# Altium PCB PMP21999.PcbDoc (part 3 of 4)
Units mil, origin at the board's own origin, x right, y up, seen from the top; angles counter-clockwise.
Board outline 7450 x 5800 mil, 6 copper layers (Top Layer, Signal Layer 3, Signal Layer 1, Signal Layer 2, Signal Layer 4, Bottom Layer), stack 66 mil thick; 237 components, 96 nets, 712 pads, 268 vias.
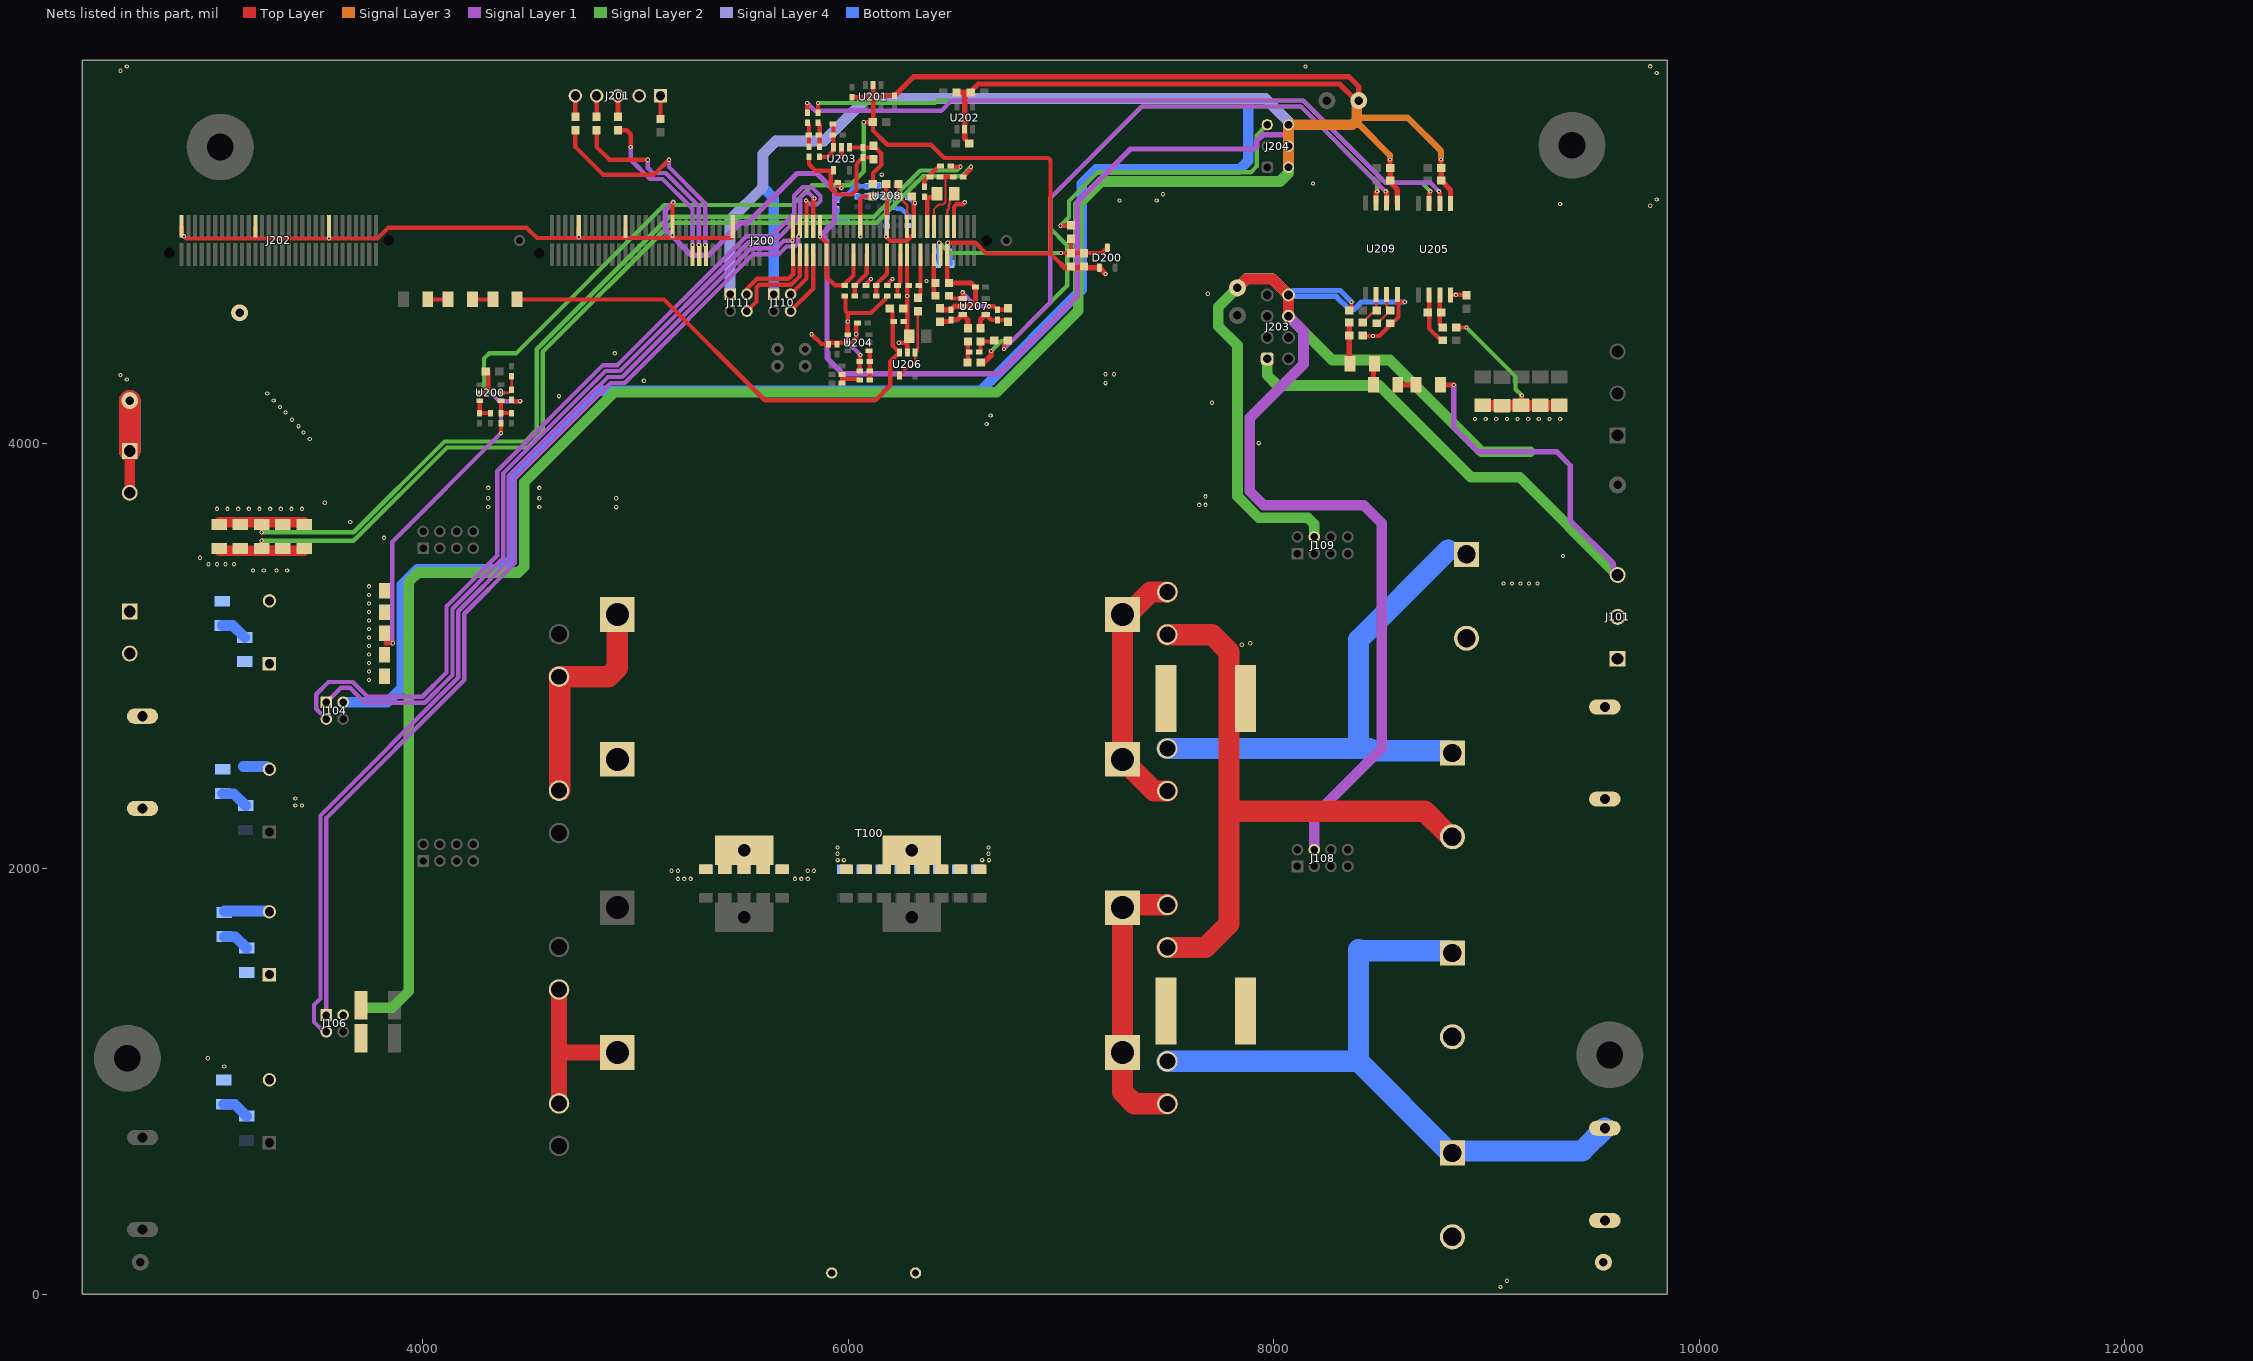
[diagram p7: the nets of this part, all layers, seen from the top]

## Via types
v1: diameter 20, hole 10, Top Layer to Bottom Layer, 268 vias

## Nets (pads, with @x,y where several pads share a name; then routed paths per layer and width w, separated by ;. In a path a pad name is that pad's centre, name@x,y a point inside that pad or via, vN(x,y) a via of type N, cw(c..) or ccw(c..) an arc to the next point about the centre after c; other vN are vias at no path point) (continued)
ISNS_REC_SEC: C220.1 R218.2 R227.2 U203.1 | length 329.1
  Top Layer w20: U203.1@6006.86,5389.75 R227.2@6126.27,5389.75 ; R218.2@6116.51,5219 6116.51,5268.53 6155.52,5307.55 6155.52,5361.72 R227.2@6119.62,5397.63
ISNS_SEC_TANK: C221.1 R200.2 R215.2 R228.2 U204.1 | length 693.2
  Top Layer w12: R228.2@6054.38,4383.53 v1@6054.38,4408.21
  Top Layer w20: R215.2@5984.38,4691.87 5984.38,4685.5 5988,4681.87 5988,4621.87 5997.81,4612.07 ; U204.1@5997.81,4509.28 5997.81,4612.07 ; C221.1@6054.38,4339.59 6054.38,4410.18 v1(6058,4413.8) ; R200.2@6184.38,4691.87 6184.38,4688.25 6108.2,4612.07 5997.81,4612.07
  Signal Layer 1 w20: v1(5998,4571.87) 5998,4473.8 v1(6058,4413.8)
Leg_1_Prim: QPL1H_S.1 QPL1L_D.1 T100.1 T100.5 | length 1077.4
  Top Layer w100: QPL1L_D.1@4641.17,2902.12 QPL1L_D.1@4644.2,2902.12 ; QPL1H_S.1@4644.2,2367.09 QPL1L_D.1@4644.2,2902.12 ; T100.1@4915.35,3194.88 4915.35,2944.02 4873.46,2902.12 QPL1L_D.1@4644.2,2902.12
Leg_1_Sec: QSL1H_S.1 QSL1L_D.1 T100.4 T100.8 | length 1316
  Top Layer w100: QSL1H_S.1@7500,894.88 7345.12,894.88 7289.37,950.63 T100.8@7289.37,1135.83 T100.4@7289.37,1816.93 7302.36,1829.92 QSL1L_D.1@7500,1829.92
Leg_2_Prim: QPL2H_S.1 QPL2L_D.1 T100.2 | length 812.9
  Top Layer w75: QPL2L_D.1@4641.17,1432.05 4641.17,1130 ; QPL2H_S.1@4644.2,897.01 4641.17,900.04 4641.17,1130 ; T100.2@4915.35,1135.83 4646.99,1135.83 4641.17,1130
Leg_2_Sec: QSL2H_S.1 QSL2L_D.1 T100.3 T100.7 | length 1191.9
  Top Layer w100: QSL2H_S.1@7500,2364.96 7438.19,2364.96 T100.3@7289.37,2513.78 7289.37,3168.11 7421.26,3300 QSL2L_D.1@7500,3300
NetC100_2: C100.2 C105.2 C108.2 C109.2 C110.2 C113.2 C114.2 C115.2 C122.2 C126.2 C128.2 C130.2 C132.2 C134.2 C136.2 C138.2 pad.1@6299.21,2086.61
  other v1: 5950.92,2040 5980,2040 6630,2040 6661.81,2040 5950,2070 6660,2070 5950,2100 6659.37,2100
NetC101_2: C101.2 C111.1 R105.1 R110.2
  other v1: 3067.48,1070 2990,1109.29
NetC102_2: C102.2 C112.1 R106.1 R111.2 | length 125.2
  Bottom Layer w50: 3157.48,2480.18 3264.94,2480.18 C102.2@3277.48,2467.64
NetC127_1: C127.1 C129.1 C131.1 C133.1 C135.1 C137.1 C139.1 C141.1 C143.1 C145.1 pad.1@5511.81,2086.61
  other v1: 5200,1952.35 5230,1952.35 5260,1952.35 5750.6,1952.35 5780,1952.35 5810,1952.35 5169.85,1990 5200,1990 5810,1990 5840,1990
NetC200_1: C200.1 J200.24 R200.1 | length 198.9
  Top Layer w20: R200.1@6231.63,4691.87 C200.1@6231.63,4741.87 6245.52,4755.77 J200.24@6245.52,4885.06
NetC202_1: C202.1 C204.1 C205.1 D200.3 J200.12 R206.1 R216.2 | length 1040.9
  Top Layer w20: v1(6428,4941.87) 6434.5,4935.38 J200.12@6434.5,4885.06 ; v1(6999.5,4893.37) R216.2@7048,4893.37 ; R206.1@7048,4960.38 R216.2@7048,4893.37 ; D200.3@7218,4919.12 7192.26,4893.37 R216.2@7048,4893.37
  Signal Layer 2 w20: v1(6428,4941.87) 6476.51,4893.37 v1(6999.5,4893.37)
  Bottom Layer w20: C205.1@6424.38,4849.75 C204.1@6424.38,4901.87 6424.38,4938.25 v1(6428,4941.87)
NetC203_1: C203.1 R202.2 R211.1 | length 132.7
  Top Layer w20: R211.1@6358,5205.5 6358,5233.53 6426.35,5301.87 R202.2@6434.38,5301.87
NetC203_2: C203.2 J200.13 R209.2 | length 331.2
  Top Layer w10: J200.13@6403,5018.92 6403,5099.09 6425.78,5121.87 6447.55,5121.87 6458,5132.33 6458,5251.87
  Top Layer w20: C203.2@6431.63,5251.87 6458,5251.87 R209.2@6494.38,5251.87
NetC206_2: C206.2 J200.14 R207.1 | length 184.3
  Top Layer w20: R207.1@6403,4700.77 J200.14@6403,4885.06
NetC207_1: C207.1 J200.18 R208.1 | length 206.7
  Top Layer w20: R208.1@6328,4683.37 6340.01,4695.38 J200.18@6340.01,4885.06
NetC208_1: C208.1 J200.21 R214.2 | length 217.7
  Top Layer w12: R214.2@6236.51,5219 C208.1@6236.51,5159 6278,5117.5 6278,5019.9 J200.21@6277.02,5018.92
NetC209_1: C209.1 J200.27 R218.1 | length 197
  Top Layer w12: C209.1@6176.51,5159 C209.1@6179.5,5159
  Top Layer w20: C209.1@6179.5,5161.99 R218.1@6179.5,5219 ; J200.27@6182.53,5018.92 C209.1@6182.53,5155.97
NetC210_1: C210.1 J200.34 R215.1 | length 217.2
  Top Layer w20: R215.1@6031.63,4691.87 C210.1@6031.63,4741.87 6032.1,4741.87 6050.76,4760.53 6050.76,4761.09 6061.23,4771.56 6061.78,4771.56 6088.04,4797.82 J200.34@6088.04,4885.06
NetC211_1: C211.1 J200.28 R217.1 | length 214.3
  Top Layer w20: R217.1@6131.63,4691.87 C211.1@6131.63,4741.87 6131.63,4745.5 6182.53,4796.4 J200.28@6182.53,4885.06
NetC220_2: C220.2 R227.1 R234.2 U203.4 | length 604
  Top Layer w20: R234.2@5816.35,5345.38 5816.35,5310.65 5846.88,5280.13 5929.68,5280.13 5918,5268.45 5918,5199 5948.38,5168.63 5980.59,5168.63 5980.96,5169 6018,5169 6039.82,5190.81 6039.82,5313.38 C220.2@6068.95,5342.51 R227.1@6118.95,5342.51
NetC221_2: C221.2 R228.1 R231.2 U204.4 | length 129.2
  Top Layer w20: R231.2@6101.63,4301.87 C221.2@6101.63,4339.59 U204.4@6101.63,4431.05
NetC227_1: C227.1 R230.2 R231.1 | length 122.8
  Top Layer w20: R230.2@5971.63,4281.87 5971.63,4301.87 ; C227.1@5971.63,4321.87 5971.63,4301.87 ; R231.1@6054.38,4301.87 5971.63,4301.87
NetC228_1: C228.1 R232.2 U205.2 | length 245
  Top Layer w20: U205.2@8730.89,4697.01 8730.89,4539.06 8786.4,4483.54 R232.2@8794.9,4483.54
NetC228_2: C228.2 R237.2 U205.3 | length 159.3
  Top Layer w20: U205.3@8780.89,4697.01 8780.89,4557.56 R237.2@8794.9,4543.54
NetC229_1: C229.1 R233.2 R234.1 | length 116.2
  Top Layer w20: R233.2@5808,5505.38 5816.35,5497.03 R234.1@5816.35,5392.62
NetC229_2: C229.2 R235.2 R236.1 | length 116.2
  Top Layer w20: R235.2@5858,5505.38 5866.35,5497.03 R236.1@5866.35,5392.62
NetC230_1: C230.1 R236.2 R238.2 U203.3 | length 196.9
  Top Layer w19.68: R236.2@5866.35,5345.38 5901.51,5345.38 5931.55,5375.42 U203.3@5931.55,5390.27 C230.1@5931.55,5494.7
NetC232_2: C232.2 R242.1 R253.2 U207.4 | length 199.5
  Top Layer w20: U207.4@6646.55,4605.46 6672.77,4579.23 R242.1@6752.41,4579.23
  Top Layer w25: R253.2@6622.41,4532.72 6622.41,4581.32 U207.4@6646.55,4605.46
NetC233_1: C233.1 R244.2 R254.2 U208.1 | length 294.1
  Bottom Layer w20: C233.1@6041.37,5160.14 6199.74,5160.14 6219.85,5140.02 U208.1@6219.85,5111.68 6229.66,5101.87 6250.01,5101.87 R254.2@6281.63,5070.26
NetC233_2: C233.2 R244.1 R249.2 U208.4 | length 216.8
  Bottom Layer w20: R249.2@5948,5145.5 5973.63,5171.13 5997.26,5171.13 C233.2@6033.52,5207.39 ; C233.2@6041.37,5207.39 6140.37,5207.39 U208.4@6145.05,5212.07
NetC240_1: C240.1 R248.2 R249.1 | length 102.8
  Bottom Layer w20: R249.1@5948,5098.25 R248.2@5948,5045.5 C240.1@5998,5045.5
NetC241_1: C241.1 R246.1 R255.2 U206.3 | length 2374.7
  Top Layer w20: R246.1@4444.33,4675.42 5134.46,4675.42 5608,4201.87 6128,4201.87 6198,4271.87 6198,4383.41 U206.3@6240.6,4426.01 6210.13,4456.48 6210.13,4576.13 6208,4578.25 6208,4620.38 R255.2@6196.51,4631.87
NetC242_1: C242.1 R251.2 U209.2 | length 161.1
  Top Layer w12: R251.2@8417.89,4566.34 8418.7,4566.34 8451.45,4599.1 8451.45,4599.9 8478.6,4627.05 8481.4,4627.05 U209.2@8481.4,4698.98
NetC242_2: C242.2 R259.2 U209.3 | length 170.1
  Top Layer w12: R259.2@8484.9,4563.54 8487.89,4563.54 C242.2@8547.89,4623.54 8531.4,4640.04 U209.3@8531.4,4698.98
NetC243_1: C243.1 R252.2 R253.1 | length 108
  Top Layer w20: C243.1@6622.41,4435.48 R253.1@6622.41,4477.6 6682.24,4477.6 R252.2@6686.51,4481.87
NetC243_2: C243.2 R256.2 R257.1 | length 100.5
  Top Layer w20: R256.2@6562.41,4384.98 R257.1@6562.41,4485.48
NetC244_1: C244.1 R257.2 R260.2 U207.3 | length 202.7
  Top Layer w25: R260.2@6432.41,4571.36 6474.54,4571.36 C244.1@6482.41,4579.23 6512.06,4579.23 U207.3@6538.28,4605.46 6562.41,4581.32 R257.2@6562.41,4532.72
NetJ200_15: J200.15 R204.1 R211.2 | length 166.5
  Top Layer w19.68: R211.2@6368,5155.38 R204.1@6401.51,5155.38 ; J200.15@6371.51,5018.92 6371.51,5151.87
NetJ201_1: J201.1 R219.1 | length 98.5
  Top Layer w20: R219.1@5118,5523.37 J201.1@5118,5621.87
NetJ201_3: J201.3 R220.2 | length 88.5
  Top Layer w25: R220.2@4918,5533.37 J201.3@4918,5621.87
NetJ201_4: J201.4 R221.2 | length 88.5
  Top Layer w20: R221.2@4818,5533.37 J201.4@4818,5621.87
NetJ201_5: J201.5 R224.2 | length 88.5
  Top Layer w20: R224.2@4718,5533.37 J201.5@4718,5621.87
NetR100_1: R100.1 R105.2 | length 130.1
  Bottom Layer w50: R105.2@3066.3,892.91 3117.4,892.91 R100.1@3173.23,837.09
NetR101_1: R101.1 R106.2 | length 131.4
  Bottom Layer w50: R106.2@3060,2352.91 3112.4,2352.91 R101.1@3168.23,2297.09
NetR110_1: R110.1 R114.2 | length 127.8
  Bottom Layer w50: R114.2@3067.48,1680.34 3119.97,1680.34 R110.1@3173.23,1627.09
NetR111_1: R111.1 R115.2 | length 127.4
  Bottom Layer w50: R115.2@3059.21,3142.91 3107.64,3142.91 R111.1@3163.46,3087.09
NetR201_1: R201.1 R212.2 U200.4 | length 108.8
  Top Layer w20: R212.2@4368.52,4141.13 R201.1@4418.52,4141.13 ; R212.2@4368.72,4141.33 U200.4@4368.72,4200.11
NetR203_1: R203.1 R213.2 U200.5 | length 118.2
  Top Layer w12: U200.5@4368.72,4237.51 4404.9,4237.51 R213.2@4418.52,4251.13 R203.1@4418.52,4313.89
NetR205_1: R205.1 R210.2 U200.3 | length 108.8
  Top Layer w20: U200.3@4268.33,4200.11 4268.33,4141.33 R210.2@4318.33,4141.33
NetR233_1: R233.1 U205.6 | length 3286
  Top Layer w20: R233.1@5808,5552.62 v1(5808,5599) ; v1(8776.4,5183.54) 8780.89,5179.06 U205.6@8780.89,5126.14
  Signal Layer 1 w20: v1(5808,5599) 5845.13,5561.87 6437.37,5561.87 6485.5,5610 8139.36,5610 8525.82,5223.54 8736.4,5223.54 v1(8776.4,5183.54)
NetR235_1: R235.1 U205.7 | length 3165.7
  Top Layer w20: R235.1@5858,5552.62 v1(5858,5599) ; U205.7@8730.89,5126.14 8730.89,5178.03 v1(8736.4,5183.54)
  Signal Layer 2 w20: v1(5858,5599) 6408.75,5599 6419.75,5610 8139.36,5610 8525.82,5223.54 8696.4,5223.54 v1(8736.4,5183.54)
NetR240_1: R240.1 R243.2 | length 95.8
  Top Layer w20: R240.1@4024.33,4675.42 R243.2@4120.16,4675.42
NetR241_1: R241.1 R245.2 | length 85.8
  Top Layer w25: R245.2@8583.48,4273.54 R241.1@8669.31,4273.54
NetR243_1: R243.1 R246.2 | length 95.8
  Top Layer w20: R243.1@4234.33,4675.42 R246.2@4330.16,4675.42
NetR245_1: R245.1 R250.2 | length 95.8
  Top Layer w25: R245.1@8469.31,4273.54 R250.2@8469.31,4369.37
NetR250_1: R250.1 R251.1 R258.2 | length 171.3
  Top Layer w25: R250.1@8354.9,4377.95 R258.2@8354.9,4506.34 R251.1@8354.9,4549.26
NetR252_1: R252.1 U209.6 | length 2822.6
  Top Layer w20: v1(6732.41,4442.86) 6732.41,4464.79 R252.1@6749.5,4481.87
  Top Layer w25: v1(8526.4,5183.54) 8531.4,5178.54 U209.6@8531.4,5128.11
  Signal Layer 1 w20: v1(6732.41,4442.86) 6950,4660.44 6950,5152.13 7380,5582.13 8127.81,5582.13 v1(8526.4,5183.54)
NetR256_1: R256.1 U209.7 | length 2980.3
  Top Layer w25: R256.1@6616.04,4378.6 6638.16,4378.6 6672.41,4412.86 v1(6672.41,4432.86) ; U209.7@8481.4,5128.11 8481.4,5178.54 v1(8486.4,5183.54)
  Signal Layer 2 w20: v1(6672.41,4432.86) 6719.56,4480 6769.56,4480 7030,4740.44 7030,4929.46 6950.76,5008.7 6950.76,5152.89 7380,5582.13 8127.81,5582.13 8486.4,5223.54 v1(8486.4,5183.54)
PGND: C111.2 C112.2 C120.2 C121.2 C147.2 C200.2 C201.1 C202.2 C204.2 C205.2 C206.1 C207.2 C208.2 C209.2 C210.2 C211.2 C214.1 C215.2 C216.1 C217.2 C218.1 C219.1 C223.2 C224.1 C225.2 C226.2 C231.2 C234.2 C236.2 C237.1 C238.2 C239.2 C241.2 C244.2 C245.2 C246.2 D200.1 J104.2 J106.2 J110.1 J111.1 J200.7 J200.10 J200.19 J200.22 J200.35 J200.38 J200.46 J200.47 J200.65 J200.83 J200.97 J200.111 J201.2 J202.135 J202.157 J202.179 J204.2 J204.4 J204.6 R103.1 R107.1 R109.1 R113.1 R114.1 R115.1 R117.1 R118.1 R119.1 R120.1 R121.1 R122.1 R209.1 R212.1 R213.1 R216.1 R239.1 R255.1 R260.1 R261.1 TP105.1 TP106.1 U200.2 U201.2 U202.2 U203.2 U204.2 U205.5 U206.2 U207.2 U208.2 U209.5 | length 50762.4
  Top Layer w19.68: v1@3560.48,4964.35 J202.135@3560.48,5019.79
  Top Layer w20: J202.179@2867.57,4982.31 J202.179@2867.57,5019.79 ; 2888,4961.87 3788,4961.87 3838,5011.87 4489.82,5011.87 4538,4963.69 5449.82,4963.69 J200.65@5458,4971.87 ; J202.157@3214.03,4967.9 J202.157@3214.03,5019.79 ; R109.1@3243.46,3494.17 R109.1@3243.46,3504.02 v1(3243.46,3541.1) ; 3825.71,3059.25 v1(3860,3059.25) ; U200.2@4268.33,4237.51 4298.52,4237.51 v1(4308.52,4247.51) C201.1@4308.52,4337.51 ; v1(4368.52,4047.51) R212.1@4368.52,4093.89 ; R213.1@4418.52,4203.89 4424.9,4197.51 v1(4458.52,4197.51) ; v1(4733.71,4967.98) J200.111@4733.71,5018.92 ; J200.97@4954.19,4967.51 J200.97@4954.19,5018.92 ; J200.83@5174.66,4967.03 J200.83@5174.66,5018.92 5174.66,5128.53 v1(5178,5131.87) ; J200.65@5458.12,4971.99 J200.65@5458.12,5018.92 ; v1(5828,4511.87) 5874.38,4465.5 R239.1@5908,4465.5 ; J200.47@5867.57,5018.92 5867.57,4972.31 v1(5868,4971.87) 5899.07,4940.81 J200.46@5899.07,4885.06 5899.07,4780.81 5938,4741.87 C210.2@5984.38,4741.87 5984.38,4747.47 6025.05,4788.14 J200.38@6025.05,4885.06 ; R239.1@5914.38,4471.87 U204.2@5997.81,4471.87 6018,4471.87 6038,4491.87 v1(6038,4511.87) C226.2@6038,4558.37 ; C217.2@6018,5625.38 6114.39,5625.38 ; v1(6058,4971.87) 6056.55,4973.33 J200.35@6056.55,5018.92 6056.55,5147.54 6068,5159 C209.2@6116.51,5159 ; v1(6073.59,5508.02) C214.1@6115.52,5508.02 ; C211.2@6084.38,4741.87 6088,4745.5 6088,4751.87 v1(6108,4771.87) ; C214.1@6116.51,5509 6116.51,5469.71 6183.59,5402.62 6389.57,5402.62 6452.05,5340.14 6940.32,5340.14 6950.76,5329.7 6950.76,4891.87 ; C214.1@6118,5510.5 U201.2@6118,5683.13 ; 6121.63,5632.62 C215.2@6218,5632.62 ; v1(6178,4971.87) 6198,4951.87 6278,4951.87 6308.52,4982.39 J200.19@6308.52,5018.92 6308.52,5149.98 C208.2@6299.5,5159 ; C200.2@6184.38,4741.87 6184.38,4748.25 v1(6208,4771.87) ; v1(6238,4471.87) 6278,4471.87 U206.2@6278,4426.01 ; C207.2@6277.02,4749.24 J200.22@6277.02,4885.06 ; C234.2@6278,4516.01 C207.2@6278,4735.5 ; C206.1@6466,4760.77 J200.10@6466,4885.06 v1@6466,4939.87 ; v1(6468,4941.87) 6598,4941.87 6648,4891.87 6950.76,4891.87 ; J200.7@6497.49,5018.92 6497.49,5111.36 6508.63,5122.5 6538.63,5122.5 v1(6548,5131.87) ; R209.1@6541.63,5251.87 6578,5288.25 v1(6578,5299) ; 7000.76,4841.87 6950.76,4891.87
  Top Layer w25: C225.2@5951.71,5226.13 5951.71,5215.3 v1(5968,5199) ; v1(5968.95,5345.97) U203.2@5968.95,5390.27 ; C215.2@6218,5632.62 6307.26,5721.87 8354.52,5721.87 8400,5676.4 TP106.1@8400,5610 8388.07,5610 8310,5688.07 6611.38,5688.07 6576.51,5653.21 C216.1@6576.51,5649 C218.1@6509.5,5649 ; R260.1@6432.41,4626.48 C244.2@6482.41,4626.48 6498.79,4642.86 U207.2@6538.28,4642.86 6572.41,4642.86 6598.79,4669.23 C238.2@6598.79,4732.86 6578.79,4752.86 C206.1@6473.91,4752.86 ; 6548,5648.98 U202.2@6548,5474.87 6548,5430.5 C219.1@6569.5,5409 ; 7000.76,4841.87 7018,4824.63 D200.1@7180.6,4824.63 v1(7210,4795.23) ; C236.2@8546.4,5295.04 v1(8546.4,5333.54) ; C236.2@8547.89,5293.54 8547.89,5224.85 8581.4,5191.34 U209.5@8581.4,5128.11 ; C223.2@8786.4,5295.04 v1(8786.4,5333.54) ; C223.2@8787.89,5293.54 C224.1@8787.89,5233.54 8830.89,5190.55 U205.5@8830.89,5126.14
  Top Layer w50: R107.1@3043.46,3494.17 3243.46,3494.17 R113.1@3443.46,3494.17
  Signal Layer 1 w20: v1(3860,3059.25) 3857.95,3061.3 3857.95,3536.94 v1(4368.52,4047.51) 4368.52,4197.31 ; v1(4308.52,4247.51) 4358.52,4197.51 v1(4458.52,4197.51)
  Signal Layer 1 w25: v1(5178,5131.87) 5140.88,5094.75 5140.88,5005.49 5263.49,4882.87 5342.55,4882.87 5494.91,5035.24 5527.95,5035.24 5760.26,5267.55 5853.95,5267.55 5936.19,5185.31 5936.19,5038.6 5870.5,4972.91 5879.18,4972.91 5900.88,4951.21 5900.88,4400.1 5974.41,4326.56 6710.87,4326.56 7077.13,4692.81 7077.13,5133.62 7326.38,5382.87 7910,5382.87 7920,5392.87 7920,5420 7949,5449 8069.78,5449
  Signal Layer 1 w50: J204.2@8069.78,5296.48 J204.4@8069.78,5396.48 8069.78,5449 J204.6@8069.78,5496.48
  Signal Layer 2 w20: v1(3243.46,3541.1) 3675.72,3541.1 4114.62,3980 4492.5,3980 4564.62,4052.12 4564.62,4430 5170.74,5036.13 6132.84,5036.13 6350.71,5254 6533,5254 v1(6578,5299) ; v1(4308.52,4247.51) 4288.52,4267.51 4288.52,4397.51 4313.14,4422.13 4438.48,4422.13 5136.11,5119.75 5738,5119.75 5830.13,5211.87 6008,5211.87 6073.59,5277.46 v1(6073.59,5508.02)
  Signal Layer 2 w50: 3720,1346.04 3856.79,1346.04 3935.04,1424.29 3935.04,3348.19 3978.85,3392 4450,3392 4477.15,3419.15 4477.15,3816.06 4901.08,4240 6698.13,4240 7080.8,4622.68 7080.8,5120.8 7190,5230 8030,5230 8069.78,5269.78 J204.2@8069.78,5296.48 J204.4@8069.78,5396.48 J204.6@8069.78,5496.48
  Signal Layer 3 w29.53: 8370,5496.48 8403.52,5496.48 8546.4,5353.6 v1(8546.4,5333.54) ; 8390,5530 8629.94,5530 8786.4,5373.54 v1(8786.4,5333.54)
  Signal Layer 3 w50: J204.2@8069.78,5296.48 J204.4@8069.78,5396.48 J204.6@8069.78,5496.48 8370,5496.48 8390,5516.48 8390,5530 TP106.1@8390,5600
  Signal Layer 4 w20: 3243.46,3522.56 v1(3243.46,3541.1)
  Signal Layer 4 w50: J111.1@5444.68,4699.37 5444.68,5049.17 5598.79,5203.28 5598.79,5358.79 5660,5420 5884.8,5420 6084.8,5620 7960,5620 8069.78,5510.22 J204.6@8069.78,5496.48 J204.4@8069.78,5396.48 J204.2@8069.78,5296.48
  Bottom Layer w20: v1(6178,4971.87) 6178,5036.94 ; C239.2@6278,5158.25 6308.24,5128.02 v1(6314.11,5128.02) ; v1(6468,4941.87) 6471.63,4938.25 C204.2@6471.63,4901.87 ; C205.2@6479.5,4841.87 C204.2@6479.5,4894
  Bottom Layer w25: 6181.63,5036.94 U208.2@6181.63,5110.85
  Bottom Layer w50: R114.1@3067.48,1800.93 3280,1800.93 C111.2@3280,1797.64 ; J104.2@3626.46,2782.13 3834.25,2782.13 3902.13,2850 3902.13,3333.97 3976.03,3407.87 4373.17,3407.87 4419.27,3453.97 4419.27,3840.03 4826.03,4246.79 6623.07,4246.79 7098.06,4721.78 7098.06,5219.91 7166.03,5287.87 7840,5287.87 7880,5327.87 7880,5620 ; J110.1@5650.63,4699.37 5650.63,5151.44 5600,5202.07 5600,5360 5660,5420 5884.8,5420 6084.8,5620 7880,5620 ; J204.2@8069.78,5296.48 J204.4@8069.78,5396.48 J204.6@8069.78,5496.48 8069.78,5510.22 7960,5620 7880,5620
  other v1: 3401.95,2297.09 3433.46,2297.09 3401.95,2330 3747.95,2886.85 3747.95,2926.85 3747.95,2966.85 3747.95,3006.85 3747.95,3046.85 3747.95,3086.85 3747.95,3126.85 3747.95,3166.85 3747.95,3206.85 3747.95,3246.85 3747.95,3286.85 3747.95,3326.85 3203.46,3401.1 3253.46,3401.1 3313.46,3401.1 3363.46,3401.1 2993.46,3431.1 3033.46,3431.1 3073.46,3431.1 3113.46,3431.1 2953.46,3461.1 3818.9,3554.96 3660,3629.96 4910,3699.03 4308.67,3700 4548.67,3700 3540,3720 4308.67,3741.2 4548.67,3741.2 4910,3741.2 4308.67,3790 4548.67,3790 6651.02,4090 6669.74,4130 4641.17,4221.01 7210,4281.87 5040,4293.52 2610,4298.91 2580,4320 7210,4324 7250,4324 4903.08,4422.13 6278,4691.87 6368,4761.87 3560,4961.87 2877.79,4972.09 5174.66,4977 9770,5115.5 9346.4,5123.54 7275.07,5140.22 7450,5140 9800,5145.5 7480,5170 8185.39,5220 6158,5261.87 6548,5520 9800,5740 2580,5750 2610,5770 8150,5770 9770,5771
PRI_FAULT: J200.74 R224.1 | length 1120.3
  Top Layer w20: R224.1@4718,5470.38 4718,5391.87 4848,5261.87 5088,5261.87 v1(5158,5331.87) ; v1(5328,4931.87) 5332.14,4927.74 J200.74@5332.14,4885.06
  Signal Layer 1 w20: v1(5158,5331.87) 5158,5297.46 5328,5127.46 v1(5328,4931.87)
PWM1A: J104.1 J200.49 | length 3954.4
  Top Layer w20: J200.49@5836.07,5018.92 5836.07,5143.88 v1(5842.41,5150.22)
  Signal Layer 1 w20: J104.1@3547.72,2782.13 3615.59,2850 3660,2850 3730,2780 4010,2780 4140,2910 4140,3221.48 4378.52,3460 4378.52,3856.91 4860.23,4338.62 4927.16,4338.62 5532.66,4944.12 5651.41,4944.12 5774.54,5067.25 5774.54,5152.96 5798,5176.43 5816.21,5176.43 v1(5842.41,5150.22)
PWM1B: J104.3 J200.51 | length 4261.8
  Top Layer w20: v1(5802.41,5140.22) 5804.58,5138.05 J200.51@5804.58,5018.92
  Signal Layer 1 w20: J104.3@3547.72,2703.38 3547.58,2703.38 3500,2750.96 3500,2820 3557.87,2877.87 3671.55,2877.87 3741.55,2807.87 3998.45,2807.87 4112.13,2921.55 4112.13,3233.02 4350.65,3471.55 4350.65,3868.46 4848.69,4366.5 4915.62,4366.5 5521.11,4971.99 5638.66,4971.99 5746.67,5080 5746.67,5164.51 5786.46,5204.3 5827.75,5204.3 5870.29,5161.77 5870.29,5138.67 5853.96,5122.35 5820.29,5122.35 v1(5802.41,5140.22)
PWM2A: J106.1 J200.53 | length 4760.5
  Top Layer w20: v1(5768,4971.87) 5773.08,4976.95 J200.53@5773.08,5018.92
  Signal Layer 1 w20: J106.1@3547.72,1312.05 3547.72,2238.88 4195.75,2886.91 4195.75,3198.38 4434.27,3436.91 4434.27,3833.82 4883.32,4282.87 4950.25,4282.87 5555.75,4888.37 5674.5,4888.37 5710.13,4924 5749.55,4924 5765.88,4940.33 5765.88,4969.75 v1(5768,4971.87)
PWM2B: J106.3 J200.55 | length 4869.5
  Top Layer w20: v1(5738,4951.87) 5740.13,4954 5740.13,5017.46 J200.55@5741.59,5018.92
  Signal Layer 1 w20: J106.3@3536.69,1233.31 3490,1280 3490,1360 3519.84,1389.84 3519.84,2250.42 4167.87,2898.45 4167.87,3209.93 4406.4,3448.45 4406.4,3845.37 4871.78,4310.75 4938.71,4310.75 5544.2,4916.24 5662.95,4916.24 5698.58,4951.87 v1(5738,4951.87)
PWM3A: J110.4 J200.50 | length 308.6
  Top Layer w20: J110.4@5729.37,4620.63 5836.07,4727.33 J200.50@5836.07,4885.06
PWM3B: J110.3 J200.52 | length 216.8
  Top Layer w20: J110.3@5729.37,4699.37 5804.58,4774.58 J200.52@5804.58,4885.06
PWM4A: J111.4 J200.54 | length 454.7
  Top Layer w20: J111.4@5524.37,4620.63 5569.61,4665.87 5569.61,4731.38 5582.83,4744.61 5731.8,4744.61 5773.08,4785.89 J200.54@5773.08,4885.06
PWM4B: J111.3 J200.56 | length 362.9
  Top Layer w20: J111.3@5524.37,4699.37 5524.37,4725.57 5571.28,4772.48 5720.25,4772.48 5741.59,4793.81 J200.56@5741.59,4885.06
RTN: J103.1 J103.2 R103.2 R107.2 R109.2 R113.2 R117.2 R202.1 TP104.1 | length 5382
  Top Layer w20: v1(3243.46,3581.1) R109.2@3243.46,3618.19 R109.2@3243.46,3628.03 ; R202.1@6481.63,5301.87 6484.5,5299 v1(6528,5299)
  Top Layer w50: J103.2@2623.46,3766.54 J103.1@2623.46,3963.39 ; R107.2@3043.46,3628.03 3243.46,3628.03 R113.2@3443.46,3628.03
  Top Layer w100: J103.1@2623.46,3963.39 TP104.1@2623.46,4200
  Signal Layer 2 w20: v1(3243.46,3581.1) 3676.3,3581.1 4103.07,4007.87 4480.95,4007.87 4536.74,4063.67 4536.74,4441.55 5159.2,5064 6121.29,5064 6339.16,5281.87 6510.88,5281.87 v1(6528,5299)
  Bottom Layer w100: J103.1@2623.46,3963.39 TP104.1@2623.46,4200
  other v1: 3033.46,3691.1 3083.46,3691.1 3133.46,3691.1 3183.46,3691.1 3233.46,3691.1 3283.46,3691.1 3333.46,3691.1 3383.46,3691.1 3433.46,3691.1 3469.74,4020 3440.52,4050 3416.18,4080 3386.18,4110 3356.18,4143.54 3330,4170 3300,4200 3270,4233.54
SCI_RX0: J200.76 R221.1 | length 925.8
  Top Layer w20: R221.1@4818,5470.38 4818,5391.87 4878,5331.87 v1(5058,5331.87) ; v1(5298,4931.87) 5300.13,4929.75 5300.13,4885.57 J200.76@5300.64,4885.06
  Signal Layer 1 w20: v1(5058,5331.87) 5058,5294.67 5082.92,5269.75 5142.92,5269.75 5298,5114.67 v1(5298,4931.87)
SCI_TX0: J200.78 R220.1 | length 790.2
  Top Layer w20: R220.1@4918,5470.38 4959.5,5470.38 4978,5451.87 v1(4978,5391.87) ; v1(5268,4931.87) 5269.15,4930.73 J200.78@5269.15,4885.06
  Signal Layer 1 w20: v1(4978,5391.87) 4978,5331.87 5068,5241.87 5128,5241.87 5268,5101.87 v1(5268,4931.87)
SGND: C103.2 C104.2 C106.2 C107.2 C123.2 C124.2 C147.1 C222.1 C235.1 J108.4 J109.4 J203.6 J203.8 QSL1L_S.1 QSL2L_S.1 R102.2 R104.2 R108.2 R112.2 R116.2 R237.1 R258.1 R259.1 TP102.1 U205.4 U209.4 | length 13452.2
  Top Layer w20: C235.1@8354.9,4623.54 8366.4,4635.04 v1(8366.4,4663.54) ; R258.1@8420.69,4503.54 v1(8466.4,4503.54) 8496.4,4503.54 8547.89,4555.04 8547.89,4556.34 8549.18,4556.34 8586.4,4593.56 8586.4,4653.54 8581.4,4658.54 U209.4@8581.4,4698.98 ; 8586.4,4663.54 v1(8616.4,4663.54) ; U205.4@8830.89,4697.01 C222.1@8904.43,4697.01 ; R237.1@8857.89,4543.54 v1(8906.4,4543.54) ; R112.2@9166.4,4180.87 v1(9166.4,4223.54)
  Top Layer w50: TP102.1@7830,4730 7870,4770 7996.26,4770 J203.8@8069.78,4696.48 J203.6@8069.78,4596.48 ; R102.2@8982.79,4177.26 R112.2@9162.79,4177.26 R108.2@9252.79,4177.26 R104.2@9342.79,4177.26
  Top Layer w100: QSL1L_S.1@7500,1629.92 7679.92,1629.92 7790,1740 7790,3020 7710,3100 QSL2L_S.1@7500,3100 ; 7810,2270 8710.16,2270 C104.2@8820,2160.16
  Signal Layer 1 w20: 9166.4,4193.54 v1(9166.4,4223.54)
  Signal Layer 1 w50: TP102.1@7830,4730 7871.87,4771.87 7994.38,4771.87 J203.8@8069.78,4696.48 J203.6@8069.78,4596.48 8140,4526.26 8140,4370.22 7887.87,4118.1 7887.87,3773.97 7953.97,3707.87 8423.97,3707.87 8507.87,3623.97 8507.87,2566.03 8190.63,2248.78 J108.4@8190.63,2089.29
  Signal Layer 2 w20: v1(8906.4,4543.54) 9136.4,4313.54 9136.4,4253.54 v1(9166.4,4223.54)
  Signal Layer 2 w50: J109.4@8190.63,3559.37 8190.63,3619.37 8160,3650 7930,3650 7830,3750 7830,4460 7740,4550 7740,4640 TP102.1@7830,4730 7871.87,4771.87 7994.38,4771.87 J203.8@8069.78,4696.48 J203.6@8069.78,4596.48 8275.29,4390.97 8546.25,4390.97 8977.22,3960 9206.5,3960
  Signal Layer 3 w50: TP102.1@7830,4730 7871.87,4771.87 7994.38,4771.87 J203.8@8069.78,4696.48 J203.6@8069.78,4596.48
  Signal Layer 4 w50: TP102.1@7830,4730 7871.87,4771.87 7994.38,4771.87 J203.8@8069.78,4696.48 J203.6@8069.78,4596.48
  Bottom Layer w25: v1(8366.4,4663.54) 8312.81,4717.13 8090.43,4717.13 J203.8@8069.78,4696.48 8081.09,4696.48 8087.57,4690 8293.54,4690 8353.54,4630 8380,4630 8413.54,4663.54 v1(8616.4,4663.54)
  other v1: 9066.4,33.54 9096.4,63.54 7850,3052.74 7890,3059.25 9080,3340 9120,3340 9160,3340 9200,3339.93 9240,3339.93 9360,3470 7650,3710 7680,3710 7680,3750 7930,4000 8946.4,4113.54 8996.4,4113.54 9046.4,4113.54 9096.4,4113.54 9146.4,4113.54 9196.4,4113.54 9246.4,4113.54 9296.4,4113.54 9346.4,4113.54 7710,4190 8856.4,4697.01 7690,4702.4
VBATT: J101.1 J101.2 J101.3 J203.1 R241.2 XF103.1 XF103.2 | length 3603.8
  Top Layer w25: R241.2@8783.48,4273.54 v1(8846.4,4273.54)
  Signal Layer 1 w25: v1(8846.4,4273.54) 8846.4,4073.6 8960.03,3959.97 9328.53,3959.97 9394.62,3893.88 9394.62,3635.32 9596.4,3433.54 9596.4,3400.39 J101.3@9616.4,3380.39
  Signal Layer 2 w50: J203.1@7969.78,4396.48 7969.78,4318.98 8017.79,4270.97 8496.54,4270.97 8927.51,3840 9156.79,3840 J101.3@9616.4,3380.39
VBUS: J100.1 J100.2 XF100.1 XF100.2
VOUT: C103.1 C104.1 C106.1 C107.1 C123.1 C124.1 QSL1H_D.1 QSL2H_D.1 TP101.1 XF102.1 XF102.2 | length 5655.1
  Bottom Layer w100: QSL1H_D.1@7500,1094.88 8398.66,1094.88 ; QSL2H_D.1@7500,2564.96 8398.66,2564.96 ; C106.1@8820,1613.7 8404.96,1613.7 8398.66,1620 8398.66,1094.88 ; C104.1@8820,2553.86 8460,2553.86 8448.9,2564.96 8398.66,2564.96 ; 8820,3496.85 8398.66,3075.51 8398.66,2564.96 ; XF102.1@9556.4,780.08 9449.86,673.54 8820,673.54 8398.66,1094.88
VPRI_SENSE: R208.2 U206.1 U206.4 | length 357.2
  Top Layer w12: U206.4@6240.6,4328.41 U206.4@6240.6,4317.74 6284.74,4361.87 6297.85,4361.87 6315.41,4379.43 U206.1@6315.41,4426.01 6328,4438.61 R208.2@6328,4620.38
Vref0: J200.9 R204.2 | length 166.2
  Top Layer w12: J200.9@6466,5018.92 6466,5094.25 6473.62,5101.87 6473.62,5121.25 6478,5125.64 6478,5151.87 R204.2@6498,5171.87
VSEC_SENSE: C232.1 R207.2 R242.2 U207.1 | length 346.3
  Top Layer w20: R207.2@6473.91,4692.86 6486.51,4680.26 U207.1@6538.28,4680.26 v1(6538.28,4708.72) ; v1(6662.41,4642.86) 6686.04,4642.86 C232.1@6702.41,4626.48 R242.2@6752.41,4626.48
  Signal Layer 1 w20: v1(6538.28,4708.72) 6604.15,4642.86 v1(6662.41,4642.86)
VSEC_SENSE_2: J204.5 R206.2 | length 1347.8
  Top Layer w20: v1(6998,5021.87) R206.2@7046.51,5021.87
  Signal Layer 2 w20: v1(6998,5021.87) 7037.93,5061.8 7037.93,5138.56 7172.24,5272.87 7892.87,5272.87 7920,5300 7920,5446.7 J204.5@7969.78,5496.48
pads on no net: H200.0 H201.1 H202.0 H203.1 H204.0 H205.1 H206.0 H207.1 J105.1 J105.2 J105.3 J105.4 J105.5 J105.6 J105.7 J105.8 J107.1 J107.2 J107.3 J107.4 J107.5 J107.6 J107.7 J107.8 J108.1 J108.2 J108.5 J108.6 J108.7 J108.8 J109.1 J109.2 J109.5 J109.6 J109.7 J109.8 J200.1 J200.2 J200.3 J200.4 J200.5 J200.6 J200.8 J200.11 J200.16 J200.17 J200.20 J200.26 J200.29 J200.30 J200.31 J200.32 J200.33 J200.36 J200.37 J200.39 J200.40 J200.41 J200.42 J200.43 J200.44 J200.45 J200.57 J200.58 J200.59 J200.60 J200.61 J200.62 J200.63 J200.64 J200.66 J200.67 J200.68 J200.69 J200.70 J200.71 J200.72 J200.73 J200.75 J200.77 J200.79 J200.80 J200.81 J200.82 J200.85 J200.86 J200.87 J200.88 J200.89 J200.90 J200.91 J200.92 J200.93 J200.94 J200.95 J200.96 J200.99 J200.100 J200.101 J200.102 J200.103 J200.104 J200.105 J200.106 J200.107 J200.108 J200.109 J200.110 J200.113 J200.114 J200.115 J200.116 J200.117 J200.118 J200.119 J200.120 J200.181 J200.182 J200.185 J200.186 J202.61 J202.62 J202.121 J202.122 J202.123 J202.124 J202.125 J202.126 J202.127 J202.128 J202.129 J202.130 J202.131 J202.132 J202.133 J202.134 J202.136 J202.137 J202.138 J202.139 J202.140 J202.141 J202.142 J202.143 J202.144 J202.145 J202.146 J202.147 J202.148 J202.149 J202.150 J202.151 J202.152 J202.153 J202.154 J202.155 J202.156 J202.159 J202.160 J202.161 J202.162 J202.163 J202.164 J202.165 J202.166 J202.167 J202.168 J202.169 J202.170 J202.171 J202.172 J202.173 J202.174 J202.175 J202.176 J202.177 J202.178 J203.2 J203.3 J203.4 J203.5 T100.6 U201.4 U204.5 U208.5

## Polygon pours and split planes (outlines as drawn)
VOUT on Top Layer "VOUT" (solid, pour order 428): 7560,2510 7580,2530 7580,2950 7560,2970 7450,2970 7440,2960 7440,2540 7470,2510
Leg_2_Sec on Top Layer "LEG_2_SEC" (solid, pour order 418): 17 vertices, not listed, extent 7100,2300 7560,3390
Leg_1_Sec on Top Layer "LEG_1_SEC" (solid, pour order 400): 17 vertices, not listed, extent 7100,780 7560,1930
RTN on Top Layer "RTN" (solid, pour order 380): 2580,4260 2560,4240 2560,3740 2710,3590 3483.28,3590 3497.49,3604.21 3497.49,4039.53 3277.02,4260
Crs_1 on Top Layer "Crs_1" (solid, pour order 354): 5950,1890 5930,1870 5930,1730 5950,1710 6660,1710 6680,1730 6680,1870 6660,1890
NetC100_2 on Top Layer "C100_2" (solid, pour order 344): 5950,2150.16 5930,2130.16 5930,1980 5950.39,1959.61 6659.61,1959.61 6680,1980 6680,2130 6660,2150
PGND on Top Layer "PGND" (solid, pour order 334): 20 vertices, not listed, extent 2920,1100 3840,3530
NetC102_2 on Top Layer "C101_2" (solid, pour order 326): 2983.46,2463.86 2983.46,2883.86 3103.46,3003.86 3323.46,3003.86 3343.46,2983.86 3343.46,2443.86 3323.46,2423.86 3253.46,2423.86 3233.46,2443.86 3003.46,2443.86
NetC101_2 on Top Layer "C101_2" (solid, pour order 324): 2970,1000 2970,1420 3090,1540 3310,1540 3330,1520 3330,980 3310,960 3240,960 3220,980 2990,980
CS on Top Layer "CS" (solid, pour order 312): 17 vertices, not listed, extent 3900,1570 4710,3390
Leg_1_Prim on Top Layer "Leg_1_Prim" (solid, pour order 298): 4840,3300 4820,3280 4820,3101.26 4678.74,2960 4600,2960 4580,2940 4580,2330 4600,2310 4890,2310 5010,2430 5010,3280 4990,3300
Leg_2_Prim on Top Layer "Leg_2_Prim" (solid, pour order 286): 4610,1480 4590,1460 4590,860 4610,840 4810,840 5020,1050 5020,1220 4760,1480
VBATT on Top Layer "VBATT" (solid, pour order 238): 9636.4,2233.54 9686.4,2283.54 9686.4,3443.54 9656.4,3473.54 9536.4,3473.54 9376.4,3313.54 9376.4,2283.54 9426.4,2233.54
BATT_RTN on Top Layer "BATT_RTN" (solid, pour order 244): 8936.4,4273.54 8916.4,4293.54 8916.4,4453.54 9026.4,4563.54 9786.4,4563.54 9806.4,4543.54 9806.4,3926.4 9640,3760 9590,3760 9426.4,3923.6 9426.4,4223.54 9376.4,4273.54
NetC127_1 on Top Layer "TOP_LAYER_NETC127_1_P250" (solid, remove dead copper, pour order 250): 5180,1940 5150,1970 5150,2139.44 5170.56,2160 5850,2160 5870,2140 5870,1970 5840,1940
Crp_1 on Top Layer "TOP_LAYER_CRP_1_P270" (solid, remove dead copper, pour order 270): 5180,1890 5150,1860 5150,1730 5180,1700 5830,1700 5860,1730 5860,1870 5840,1890
VBUS on Top Layer "VBUS" (solid, pour order 282): 2510,3270 2490,3250 2490,2240 2510,2220 2840,2220 2860,2240 2860,3250 2840,3270
SGND on Top Layer "SGND" (solid, pour order 438): 30 vertices, not listed, extent 6290,10 9410,4210
SGND on Top Layer "SGND" (solid, pour order 440): 37 vertices, not listed, extent 7440,1340 8480,4160
HVBUS on Top Layer "HVBUS" (solid, pour order 492): 36 vertices, not listed, extent 2580,80 4700,2240
VOUT on Top Layer "VOUT" (solid, pour order 514): 7460,1040 7440,1060 7440,1489.66 7450.34,1500 7530,1500 7640,1390 7640,1150 7530,1040
Leg_1_Sec on Signal Layer 2 "LEG_2_SEC" (solid, pour order 422): 17 vertices, not listed, extent 7100,2300 7560,3390
VOUT on Signal Layer 2 "Vout" (solid, pour order 414): 35 vertices, not listed, extent 7440,100 9680,3570
Leg_1_Sec on Signal Layer 2 "LEG_1_SEC" (solid, pour order 406): 17 vertices, not listed, extent 7100,780 7560,1930
NetC102_2 on Signal Layer 2 "C102_2" (solid, pour order 376): 2983.46,2463.86 2983.46,2883.86 3103.46,3003.86 3323.46,3003.86 3343.46,2983.86 3343.46,2443.86 3323.46,2423.86 3253.46,2423.86 3233.46,2443.86 3003.46,2443.86
NetC101_2 on Signal Layer 2 "C101_2" (solid, pour order 366): 2970,1000 2970,1420 3090,1540 3310,1540 3330,1520 3330,980 3310,960 3240,960 3220,980 2990,980
Crs_1 on Signal Layer 2 "Crs_1" (solid, pour order 360): 5951.81,1890 5931.81,1870 5931.81,1730 5951.81,1710 6661.81,1710 6681.81,1730 6681.81,1870 6661.81,1890
NetC100_2 on Signal Layer 2 "C100_2" (solid, pour order 350): 5950,2150.16 5930,2130.16 5930,1980 5950.39,1959.61 6659.61,1959.61 6680,1980 6680,2130 6660,2150
Leg_1_Prim on Signal Layer 2 "Leg_1_Prim" (solid, pour order 304): 4840,3300 4820,3280 4820,3101.26 4678.74,2960 4600,2960 4580,2940 4580,2330 4600,2310 4890,2310 5010,2430 5010,3280 4990,3300
Leg_2_Prim on Signal Layer 2 "Leg_2_Prim" (solid, pour order 290): 4607.67,1480 4587.67,1460 4587.67,860 4607.67,840 4807.67,840 5017.67,1050 5017.67,1220 4757.67,1480
NetC127_1 on Signal Layer 2 "SIGNAL_LAYER_2_NETC127_1_P248" (solid, remove dead copper, pour order 248): 5180,1940 5150,1970 5150,2139.44 5170.56,2160 5850,2160 5870,2140 5870,1970 5840,1940
Crp_1 on Signal Layer 2 "SIGNAL_LAYER_2_CRP_1_P264" (solid, remove dead copper, pour order 264): 5180,1890 5150,1860 5150,1730 5180,1700 5830,1700 5860,1730 5860,1870 5840,1890
VBUS on Signal Layer 2 "VBUS" (solid, pour order 276): 2510,3270 2490,3250 2490,2240 2510,2220 2840,2220 2860,2240 2860,3250 2840,3270
CS on Signal Layer 2 "CS" (solid, pour order 316): 17 vertices, not listed, extent 3980,1570 4710,3350
PGND on Signal Layer 2 "PGND" (solid, pour order 338): 22 vertices, not listed, extent 2920,10 5950,3520
BATT_RTN on Signal Layer 2 "BATT_RTN" (solid, pour order 434): 8929.94,4280 8916.4,4293.54 8916.4,4453.54 9026.4,4563.54 9786.4,4563.54 9806.4,4543.54 9806.4,3926.4 9640,3760 9590,3760 9426.4,3923.6 9426.4,4223.54 9369.94,4280
VBATT on Signal Layer 2 "VBATT" (solid, pour order 444): 9636.4,2233.54 9686.4,2283.54 9686.4,3443.54 9656.4,3473.54 9536.4,3473.54 9376.4,3313.54 9376.4,2283.54 9426.4,2233.54
SGND on Signal Layer 2 "SGND" (solid, pour order 486): 26 vertices, not listed, extent 7660,1110 9410,4210
SGND on Signal Layer 2 "SGND" (solid, pour order 484): 28 vertices, not listed, extent 7440,3031.26 8480,4160
HVBUS on Signal Layer 2 "HVBUS" (solid, pour order 494): 36 vertices, not listed, extent 2580,80 4700,2240
RTN on Signal Layer 2 "RTN" (solid, pour order 524): 2580,4260 2560,4240 2560,3740 2700,3600 3479.72,3600 3497.49,3617.77 3497.49,4039.53 3277.02,4260
PGND on Signal Layer 2 "PGND" (solid, pour order 534): 27 vertices, not listed, extent 2560,3381.39 9830,5791
SGND on Signal Layer 2 "SGND" (solid, pour order 544): 24 vertices, not listed, extent 7670,4169.11 9030,4807.01
VOUT on Signal Layer 3 "Vout" (solid, pour order 412): 35 vertices, not listed, extent 7440,100 9680,3570
Leg_1_Sec on Signal Layer 3 "LEG_1_SEC" (solid, pour order 402): 17 vertices, not listed, extent 7100,780 7560,1930
NetC102_2 on Signal Layer 3 "C102_2" (solid, pour order 372): 2983.46,2463.86 2983.46,2883.86 3103.46,3003.86 3323.46,3003.86 3343.46,2983.86 3343.46,2443.86 3323.46,2423.86 3253.46,2423.86 3233.46,2443.86 3003.46,2443.86
NetC101_2 on Signal Layer 3 "C101_2" (solid, pour order 370): 2970,1000 2970,1420 3090,1540 3310,1540 3330,1520 3330,980 3310,960 3240,960 3220,980 2990,980
Crs_1 on Signal Layer 3 "Crs_1" (solid, pour order 364): 5951.81,1890 5931.81,1870 5931.81,1730 5951.81,1710 6661.81,1710 6681.81,1730 6681.81,1870 6661.81,1890
NetC100_2 on Signal Layer 3 "C100_2" (solid, pour order 346): 5950,2150.16 5930,2130.16 5930,1980 5950.39,1959.61 6659.61,1959.61 6680,1980 6680,2130 6660,2150
HVBUS on Signal Layer 3 "HVBUS" (solid, pour order 340): 34 vertices, not listed, extent 2580,80 4700,2240
Leg_1_Prim on Signal Layer 3 "Leg_1_Prim" (solid, pour order 308): 4840,3300 4820,3280 4820,3101.26 4678.74,2960 4600,2960 4580,2940 4580,2330 4600,2310 4890,2310 5010,2430 5010,3280 4990,3300
Leg_2_Prim on Signal Layer 3 "Leg_2_Prim" (solid, pour order 294): 4607.67,1480 4587.67,1460 4587.67,860 4607.67,840 4807.67,840 5017.67,1050 5017.67,1220 4757.67,1480
NetC127_1 on Signal Layer 3 "SIGNAL_LAYER_3_NETC127_1_P246" (solid, remove dead copper, pour order 246): 5180,1940 5150,1970 5150,2139.44 5170.56,2160 5850,2160 5870,2140 5870,1970 5840,1940
Crp_1 on Signal Layer 3 "SIGNAL_LAYER_3_CRP_1_P268" (solid, remove dead copper, pour order 268): 5180,1890 5150,1860 5150,1730 5180,1700 5830,1700 5860,1730 5860,1870 5840,1890
VBUS on Signal Layer 3 "VBUS" (solid, pour order 280): 2510,3270 2490,3250 2490,2240 2510,2220 2840,2220 2860,2240 2860,3250 2840,3270
BATT_RTN on Signal Layer 3 "BATT_RTN" (solid, pour order 436): 8932.43,4277.51 8916.4,4293.54 8916.4,4453.54 9026.4,4563.54 9786.4,4563.54 9806.4,4543.54 9806.4,3926.4 9640,3760 9590,3760 9426.4,3923.6 9426.4,4223.54 9372.43,4277.51
VBATT on Signal Layer 3 "VBATT" (solid, pour order 448): 9636.4,2233.54 9686.4,2283.54 9686.4,3443.54 9656.4,3473.54 9536.4,3473.54 9376.4,3313.54 9376.4,2283.54 9426.4,2233.54
SGND on Signal Layer 3 "SGND" (solid, pour order 466): 21 vertices, not listed, extent 7660,1110 9410,4210
SGND on Signal Layer 3 "SGND" (solid, pour order 464): 28 vertices, not listed, extent 7440,3031.26 8480,4160
PGND on Signal Layer 3 "PGND" (solid, pour order 504): 20 vertices, not listed, extent 2920,1100 3840,3530
CS on Signal Layer 3 "CS" (solid, pour order 508): 17 vertices, not listed, extent 3900,1570 4710,3390
RTN on Signal Layer 3 "RTN" (solid, pour order 526): 2580,4260 2560,4240 2560,3740 2700,3600 3479.72,3600 3497.49,3617.77 3497.49,4039.53 3277.02,4260
PGND on Signal Layer 3 "PGND" (solid, pour order 528): 27 vertices, not listed, extent 2560,3380.39 9830,5790
SGND on Signal Layer 3 "SGND" (solid, pour order 538): 19 vertices, not listed, extent 7670,4170 9030,4807.9
Leg_2_Sec on Signal Layer 1 "LEG_2_SEC" (solid, pour order 420): 17 vertices, not listed, extent 7100,2300 7560,3390
Leg_1_Sec on Signal Layer 1 "LEG_1_SEC" (solid, pour order 404): 17 vertices, not listed, extent 7100,780 7560,1930
NetC102_2 on Signal Layer 1 "C102_2" (solid, pour order 374): 3080,2597.32 3080,2980.39 3103.46,3003.86 3323.46,3003.86 3343.46,2983.86 3343.46,2443.86 3323.46,2423.86 3253.46,2423.86 3233.46,2443.86
NetC101_2 on Signal Layer 1 "C101_2" (solid, pour order 368): 2970,1000 2970,1420 3090,1540 3310,1540 3330,1520 3330,980 3310,960 3240,960 3220,980 2990,980
Crs_1 on Signal Layer 1 "Crs_1" (solid, pour order 362): 5951.81,1890 5931.81,1870 5931.81,1730 5951.81,1710 6661.81,1710 6681.81,1730 6681.81,1870 6661.81,1890
NetC100_2 on Signal Layer 1 "C100_2" (solid, pour order 348): 5950,2150.16 5930,2130.16 5930,1980 5950.39,1959.61 6659.61,1959.61 6680,1980 6680,2130 6660,2150
Leg_1_Prim on Signal Layer 1 "Leg_1_Prim" (solid, pour order 306): 4840,3300 4820,3280 4820,3101.26 4678.74,2960 4600,2960 4580,2940 4580,2330 4600,2310 4890,2310 5010,2430 5010,3280 4990,3300
Leg_2_Prim on Signal Layer 1 "Leg_2_Prim" (solid, pour order 292): 4607.67,1480 4587.67,1460 4587.67,860 4607.67,840 4807.67,840 5017.67,1050 5017.67,1220 4757.67,1480
NetC127_1 on Signal Layer 1 "SIGNAL_LAYER_1_NETC127_1_P252" (solid, remove dead copper, pour order 252): 5180,1940 5150,1970 5150,2139.44 5170.56,2160 5850,2160 5870,2140 5870,1970 5840,1940
Crp_1 on Signal Layer 1 "SIGNAL_LAYER_1_CRP_1_P266" (solid, remove dead copper, pour order 266): 5180,1890 5150,1860 5150,1730 5180,1700 5830,1700 5860,1730 5860,1870 5840,1890
VBUS on Signal Layer 1 "VBUS" (solid, pour order 278): 2510,3270 2490,3250 2490,2240 2510,2220 2840,2220 2860,2240 2860,3070 2660,3270
VBATT on Signal Layer 1 "VBATT" (solid, pour order 446): 9636.4,2233.54 9686.4,2283.54 9686.4,3443.54 9656.4,3473.54 9536.4,3473.54 9376.4,3313.54 9376.4,2283.54 9426.4,2233.54
SGND on Signal Layer 1 "SGND" (solid, pour order 462): 33 vertices, not listed, extent 6290,10 9410,4210
SGND on Signal Layer 1 "SGND" (solid, pour order 460): 39 vertices, not listed, extent 7438.19,1340 8480,4160
HVBUS on Signal Layer 1 "HVBUS" (solid, pour order 488): 26 vertices, not listed, extent 2580,80 4700,2240
PGND on Signal Layer 1 "PGND" (solid, pour order 502): 22 vertices, not listed, extent 2920,1100 3840,3530
PGND on Signal Layer 1 "PGND" (solid, pour order 536): 29 vertices, not listed, extent 2560,3540 9830,5791
SGND on Signal Layer 1 "SGND" (solid, pour order 546): 19 vertices, not listed, extent 7670,4169.11 9030,4807.01
Leg_2_Sec on Signal Layer 4 "LEG_2_SEC" (solid, pour order 424): 17 vertices, not listed, extent 7100,2300 7560,3390
Leg_1_Sec on Signal Layer 4 "LEG_1_SEC" (solid, pour order 408): 17 vertices, not listed, extent 7100,780 7560,1930
NetC102_2 on Signal Layer 4 "C102_2" (solid, pour order 378): 2983.46,2463.86 2983.46,2883.86 3103.46,3003.86 3323.46,3003.86 3343.46,2983.86 3343.46,2443.86 3323.46,2423.86 3253.46,2423.86 3233.46,2443.86 3003.46,2443.86
Crs_1 on Signal Layer 4 "Crs_1" (solid, pour order 358): 5951.81,1890 5931.81,1870 5931.81,1730 5951.81,1710 6661.81,1710 6681.81,1730 6681.81,1870 6661.81,1890
NetC100_2 on Signal Layer 4 "C100_2" (solid, pour order 352): 5950,2150.16 5930,2130.16 5930,1980 5950.39,1959.61 6659.61,1959.61 6680,1980 6680,2130 6660,2150
PGND on Signal Layer 4 "PGND" (solid, pour order 336): 20 vertices, not listed, extent 2920,1100 3840,3530
NetC102_2 on Signal Layer 4 "C102_2" (solid, pour order 328): 2983.46,2463.86 2983.46,2883.86 3103.46,3003.86 3323.46,3003.86 3343.46,2983.86 3343.46,2443.86 3323.46,2423.86 3253.46,2423.86 3233.46,2443.86 3003.46,2443.86
NetC101_2 on Signal Layer 4 "C101_2" (solid, pour order 322): 2970,1000 2970,1420 3090,1540 3310,1540 3330,1520 3330,980 3310,960 3240,960 3220,980 2990,980
CS on Signal Layer 4 "CS" (solid, pour order 314): 17 vertices, not listed, extent 3900,1570 4710,3390
Leg_1_Prim on Signal Layer 4 "Leg_1_Prim" (solid, pour order 302): 4840,3300 4820,3280 4820,3101.26 4678.74,2960 4600,2960 4580,2940 4580,2330 4600,2310 4890,2310 5010,2430 5010,3280 4990,3300
Leg_2_Prim on Signal Layer 4 "Leg_2_Prim" (solid, pour order 288): 4610,1480 4590,1460 4590,860 4610,840 4810,840 5020,1050 5020,1220 4760,1480
NetC127_1 on Signal Layer 4 "SIGNAL_LAYER_4_NETC127_1_P256" (solid, remove dead copper, pour order 256): 5180,1940 5150,1970 5150,2139.44 5170.56,2160 5850,2160 5870,2140 5870,1970 5840,1940
Crp_1 on Signal Layer 4 "SIGNAL_LAYER_4_CRP_1_P262" (solid, remove dead copper, pour order 262): 5180,1890 5150,1860 5150,1730 5180,1700 5830,1700 5860,1730 5860,1870 5840,1890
